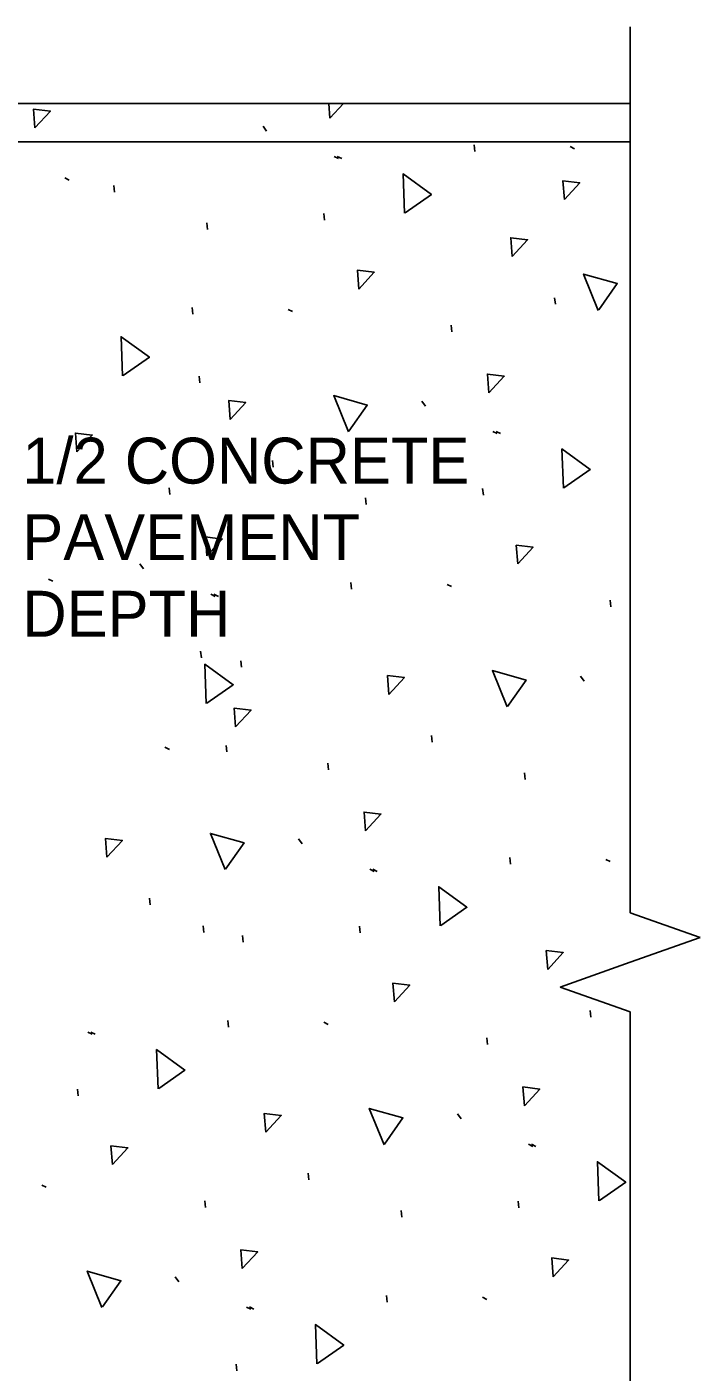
# Model space of a CAD drawing. Extents: x 49991.4 to 50021, y 49987.6 to 50011.4.
# Drawn here: x 50004.633 to 50005.512, y 49989.221 to 49990.978 of the extents above; entities that cross this region are included whole.
import ezdxf

# ---------------------------------------------------------------- set-up
doc = ezdxf.new("R2010")
doc.units = 0
for name, color, linetype in [('Level 1', 7, 'Continuous'), ('Level 2', 7, 'Continuous'), ('Level 4', 7, 'Continuous'), ('Level 6', 7, 'Continuous')]:
    doc.layers.add(name, color=color, linetype=linetype)

msp = doc.modelspace()

# ---------------------------------------------------------------- linework, layer by layer
at = {"layer": 'Level 1'}
for p, q in [((50004.3657, 49990.8781), (50005.421, 49990.8781)), ((50002.5169, 49990.8281), (50005.421, 49990.8281))]:
    msp.add_line(p, q, dxfattribs=at)
at = {"layer": 'Level 4'}
for p, q in [((50004.9415, 49990.8485), (50004.9462, 49990.842)), ((50005.2182, 49990.8155), (50005.2173, 49990.8242)), ((50005.3427, 49990.8218), (50005.3485, 49990.8189)), ((50005.0343, 49990.8089), (50005.0401, 49990.8061)), ((50005.0384, 49990.809), (50005.0442, 49990.8061)), ((50004.6824, 49990.7809), (50004.6881, 49990.7781)), ((50004.7475, 49990.7623), (50004.7466, 49990.771)), ((50005.0219, 49990.7257), (50005.0209, 49990.7344)), ((50004.869, 49990.7135), (50004.8681, 49990.7222)), ((50005.3233, 49990.6157), (50005.3224, 49990.6244)), ((50004.8498, 49990.6028), (50004.8489, 49990.6115)), ((50004.9744, 49990.6091), (50004.9801, 49990.6063)), ((50005.1882, 49990.5798), (50005.1873, 49990.5885)), ((50004.8589, 49990.513), (50004.858, 49990.5217)), ((50005.1489, 49990.4893), (50005.1537, 49990.4828)), ((50005.2417, 49990.4497), (50005.2475, 49990.4469)), ((50005.2458, 49990.4497), (50005.2516, 49990.4469)), ((50004.9549, 49990.403), (50004.954, 49990.4117)), ((50004.8198, 49990.3671), (50004.8189, 49990.3758)), ((50005.0764, 49990.3542), (50005.0755, 49990.3629)), ((50005.2293, 49990.3665), (50005.2283, 49990.3752)), ((50004.7805, 49990.2766), (50004.7853, 49990.2701)), ((50004.6611, 49990.2568), (50004.6668, 49990.2539)), ((50005.0572, 49990.2436), (50005.0563, 49990.2523)), ((50005.1818, 49990.2499), (50005.1875, 49990.247)), ((50004.8733, 49990.237), (50004.8791, 49990.2342)), ((50004.8774, 49990.237), (50004.8832, 49990.2342)), ((50005.3956, 49990.2205), (50005.3947, 49990.2292)), ((50004.8609, 49990.1538), (50004.86, 49990.1625)), ((50004.9134, 49990.1415), (50004.9125, 49990.1502)), ((50005.3563, 49990.13), (50005.3611, 49990.1236)), ((50005.1623, 49990.0438), (50005.1614, 49990.0525)), ((50004.8134, 49990.0372), (50004.8191, 49990.0343)), ((50004.8943, 49990.0309), (50004.8934, 49990.0396)), ((50005.0272, 49990.0078), (50005.0263, 49990.0165)), ((50005.2838, 49989.995), (50005.2829, 49990.0037)), ((50004.9879, 49989.9174), (50004.9927, 49989.9109)), ((50005.2646, 49989.8843), (50005.2637, 49989.893)), ((50005.3892, 49989.8906), (50005.3949, 49989.8878)), ((50005.0808, 49989.8778), (50005.0865, 49989.8749)), ((50005.0848, 49989.8778), (50005.0906, 49989.8749)), ((50004.7939, 49989.8311), (50004.793, 49989.8398)), ((50004.8643, 49989.7951), (50004.8633, 49989.8038)), ((50005.0683, 49989.7946), (50005.0674, 49989.8033)), ((50004.9154, 49989.7823), (50004.9145, 49989.791)), ((50005.3697, 49989.6846), (50005.3688, 49989.6932)), ((50004.8962, 49989.6716), (50004.8953, 49989.6803)), ((50005.0208, 49989.6779), (50005.0265, 49989.6751)), ((50004.7124, 49989.6651), (50004.7181, 49989.6622)), ((50004.7165, 49989.6651), (50004.7222, 49989.6623)), ((50005.2346, 49989.6486), (50005.2337, 49989.6573)), ((50004.6999, 49989.5819), (50004.699, 49989.5906)), ((50005.1953, 49989.5581), (50005.2001, 49989.5516)), ((50005.2882, 49989.5185), (50005.2939, 49989.5157)), ((50005.2922, 49989.5185), (50005.298, 49989.5157)), ((50004.6524, 49989.4652), (50004.6581, 49989.4624)), ((50005.0013, 49989.4719), (50005.0004, 49989.4806)), ((50004.8662, 49989.4359), (50004.8653, 49989.4446)), ((50005.1228, 49989.4231), (50005.1219, 49989.4318)), ((50005.2757, 49989.4353), (50005.2748, 49989.444)), ((50004.8269, 49989.3454), (50004.8317, 49989.3389)), ((50004.9198, 49989.3058), (50004.9255, 49989.303)), ((50004.9239, 49989.3059), (50004.9296, 49989.303)), ((50005.1036, 49989.3124), (50005.1027, 49989.3211)), ((50005.2282, 49989.3187), (50005.2339, 49989.3158)), ((50004.9073, 49989.2226), (50004.9064, 49989.2313))]:
    msp.add_line(p, q, dxfattribs=at)
for points in [[(50004.6436, 49990.8462), (50004.6417, 49990.8708), (50004.6638, 49990.8681), (50004.6436, 49990.8462)], [(50005.0289, 49990.8591), (50005.0275, 49990.8781)], [(50005.0464, 49990.8781), (50005.0289, 49990.8591)], [(50005.1264, 49990.7348), (50005.1245, 49990.786), (50005.1615, 49990.7592), (50005.1271, 49990.7352)], [(50005.3351, 49990.7526), (50005.3332, 49990.7771), (50005.3552, 49990.7745), (50005.3351, 49990.7526)], [(50005.267, 49990.6781), (50005.2651, 49990.7026), (50005.2871, 49990.7), (50005.267, 49990.6781)], [(50005.0666, 49990.6357), (50005.0648, 49990.6603), (50005.0868, 49990.6576), (50005.0666, 49990.6357)], [(50005.3794, 49990.6078), (50005.3601, 49990.6553), (50005.4041, 49990.6428), (50005.3799, 49990.6085)], [(50004.758, 49990.5221), (50004.7561, 49990.5733), (50004.7931, 49990.5465), (50004.7587, 49990.5226)], [(50005.2363, 49990.4999), (50005.2345, 49990.5245), (50005.2565, 49990.5218), (50005.2363, 49990.4999)], [(50004.8986, 49990.4654), (50004.8967, 49990.4899), (50004.9188, 49990.4873), (50004.8986, 49990.4654)], [(50005.053, 49990.4491), (50005.0338, 49990.4966), (50005.0777, 49990.484), (50005.0536, 49990.4498)], [(50004.6983, 49990.423), (50004.6964, 49990.4476), (50004.7184, 49990.4449), (50004.6983, 49990.423)], [(50005.3338, 49990.3756), (50005.3319, 49990.4268), (50005.3689, 49990.3999), (50005.3345, 49990.376)], [(50004.868, 49990.2872), (50004.8661, 49990.3118), (50004.8881, 49990.3091), (50004.868, 49990.2872)], [(50005.2741, 49990.2765), (50005.2722, 49990.301), (50005.2942, 49990.2984), (50005.2741, 49990.2765)], [(50004.8673, 49990.0943), (50004.8654, 49990.1456), (50004.9025, 49990.1187), (50004.8681, 49990.0948)], [(50005.2605, 49990.0899), (50005.2412, 49990.1373), (50005.2851, 49990.1248), (50005.261, 49990.0905)], [(50005.106, 49990.1061), (50005.1041, 49990.1307), (50005.1262, 49990.128), (50005.106, 49990.1061)], [(50004.9057, 49990.0638), (50004.9038, 49990.0883), (50004.9258, 49990.0857), (50004.9057, 49990.0638)], [(50005.0754, 49989.928), (50005.0735, 49989.9525), (50005.0955, 49989.9499), (50005.0754, 49989.928)], [(50004.8921, 49989.8772), (50004.8728, 49989.9246), (50004.9167, 49989.9121), (50004.8926, 49989.8778)], [(50004.7376, 49989.8935), (50004.7357, 49989.918), (50004.7578, 49989.9154), (50004.7376, 49989.8935)], [(50005.1728, 49989.8036), (50005.1709, 49989.8548), (50005.2079, 49989.828), (50005.1736, 49989.8041)], [(50005.3134, 49989.7469), (50005.3115, 49989.7715), (50005.3336, 49989.7688), (50005.3134, 49989.7469)], [(50005.1131, 49989.7045), (50005.1112, 49989.7291), (50005.1332, 49989.7264), (50005.1131, 49989.7045)], [(50004.8044, 49989.5909), (50004.8025, 49989.6421), (50004.8395, 49989.6153), (50004.8052, 49989.5914)], [(50005.2828, 49989.5687), (50005.2809, 49989.5933), (50005.3029, 49989.5906), (50005.2828, 49989.5687)], [(50004.945, 49989.5342), (50004.9431, 49989.5588), (50004.9652, 49989.5561), (50004.945, 49989.5342)], [(50005.0995, 49989.5179), (50005.0802, 49989.5654), (50005.1242, 49989.5529), (50005.1, 49989.5186)], [(50004.7447, 49989.4919), (50004.7428, 49989.5164), (50004.7649, 49989.5138), (50004.7447, 49989.4919)], [(50005.3802, 49989.4444), (50005.3783, 49989.4956), (50005.4153, 49989.4688), (50005.381, 49989.4448)], [(50004.9144, 49989.356), (50004.9125, 49989.3806), (50004.9346, 49989.3779), (50004.9144, 49989.356)], [(50005.3205, 49989.3453), (50005.3186, 49989.3699), (50005.3407, 49989.3672), (50005.3205, 49989.3453)], [(50004.7311, 49989.3052), (50004.7118, 49989.3527), (50004.7558, 49989.3402), (50004.7317, 49989.3059)], [(50005.0118, 49989.2317), (50005.0099, 49989.2829), (50005.0469, 49989.2561), (50005.0126, 49989.2321)]]:
    msp.add_lwpolyline(points, dxfattribs=at)
at = {"layer": 'Level 6'}
for p, q in [((50005.421, 49990.9781), (50005.421, 49989.821)), ((50005.5124, 49989.7886), (50005.421, 49989.821)), ((50005.5124, 49989.7886), (50005.421, 49989.7562)), ((50005.421, 49989.7562), (50005.3296, 49989.7238)), ((50005.421, 49989.6914), (50005.3296, 49989.7238)), ((50005.421, 49989.6914), (50005.421, 49988.5501))]:
    msp.add_line(p, q, dxfattribs=at)

# ---------------------------------------------------------------- texts
at = {"layer": 'Level 2'}
for s, p in [('1/2 CONCRETE', (50004.627, 49990.3815)), ('PAVEMENT', (50004.627, 49990.2815)), ('DEPTH', (50004.627, 49990.1815))]:
    msp.add_text(s, height=0.06, dxfattribs=at).set_placement(p)

doc.saveas('drawing.dxf')
